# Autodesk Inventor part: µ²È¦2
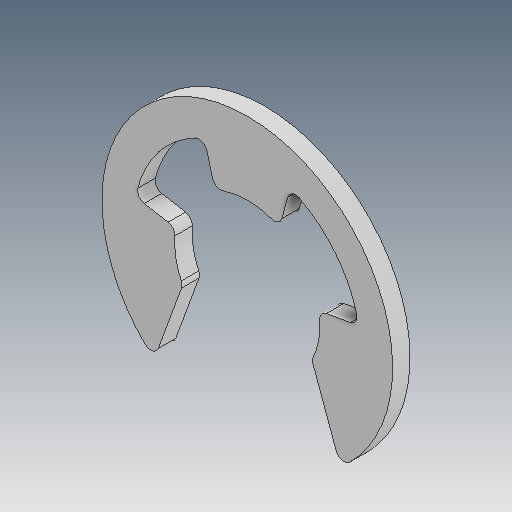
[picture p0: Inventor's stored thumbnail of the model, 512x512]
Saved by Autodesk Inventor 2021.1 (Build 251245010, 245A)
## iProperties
Created: 2014-12
Part Number: µ²È¦2
Material: Ogólny
Document SubType Name: Modeling
Designer: user
Density: 1 g/cm^3
Appearance: Domyślna
Author: user
Revision Number: ÈÎºÎ
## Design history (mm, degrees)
feature "ÊäÈë1"
node "Bryła1"
